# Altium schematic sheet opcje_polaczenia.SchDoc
size A4
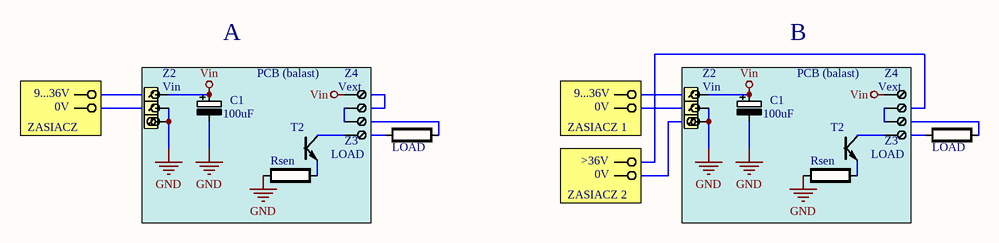
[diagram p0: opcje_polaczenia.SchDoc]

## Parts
(Parts that share a designator on the sheet are numbered #1, #2 ... from top to bottom, then left to right.)
?#1  (no value)  [P]
?#2  (no value)  [P]
?#3  (no value)  [P]
?#4  (no value)  [P]
?#5  (no value)  [P]
?#6  (no value)  [P]
C1#1  100uF  [CE6]
C1#2  100uF  [CE6]
LOAD#1  (no value)  [R4]
LOAD#2  (no value)  [R4]
Rsen#1  (no value)  [R4]
Rsen#2  (no value)  [R4]
T2#1  (no value)  [TUNIW]
T2#2  (no value)  [TUNIW]
Z2#1  Vin  [ARK3]
Z2#2  Vin  [ARK3]
Z3#1  LOAD  [ARK2]
Z3#2  LOAD  [ARK2]
Z4#1  Vext  [ARK2]
Z4#2  Vext  [ARK2]

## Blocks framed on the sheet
PCB (balast): C1#1 Rsen#1 T2#1 Z2#1 Z3#1 Z4#1
PCB (balast): C1#2 Rsen#2 T2#2 Z2#2 Z3#2 Z4#2

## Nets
GND: C1#1.2 C1#2.2 Rsen#1.2(BOT) Rsen#2.2(BOT) Z2#1.2 Z2#1.3 Z2#2.2 Z2#2.3
Vin: C1#1.1 C1#2.1 Z2#1.1 Z2#2.1 Z4#1.2 Z4#2.2
NetRsen#1_1: Rsen#1.1(TOP) T2#1.1(E)
NetRsen#2_1: Rsen#2.1(TOP) T2#2.1(E)
NetT2#1_3: T2#1.3(C) Z3#1.1
NetT2#2_3: T2#2.3(C) Z3#2.1
NetZ3#1_2: Z3#1.2 Z4#1.1
NetZ3#2_2: Z3#2.2 Z4#2.1

Not connected (* = marked no-connect by the designer): ?#1 1; ?#2 1; ?#3 1; ?#4 1; ?#5 1; ?#6 1; LOAD#1 1(TOP) 2(BOT); LOAD#2 1(TOP) 2(BOT); T2#1 2(B); T2#2 2(B)

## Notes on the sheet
- A
- B
- ZASIACZ
- 9...36V
- 0V
- ZASIACZ 1
- ZASIACZ 2
- >36V

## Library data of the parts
?#1-?#6 = P
C1#1 C1#2 = EL: Elektrolit
LOAD#1 LOAD#2 Rsen#1 Rsen#2 = R: Rezystor
T2#1 T2#2 = NPN: Tranzystor NPN
Z2#1 Z2#2 = ARK 3
Z3#1 Z3#2 Z4#1 Z4#2 = ARK2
